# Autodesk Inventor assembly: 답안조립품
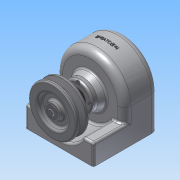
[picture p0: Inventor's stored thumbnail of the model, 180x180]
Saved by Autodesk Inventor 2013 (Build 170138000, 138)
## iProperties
Created: 2015-02
Part Number: 답안조립품
Document SubType Name: Assembly
Designer: Administrator
Author: Administrator
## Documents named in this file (14)
- C:\Documents and Settings\Administrator\바탕 화면\450214V1015\답안조립품.iam
- C:\Documents and Settings\Administrator\바탕 화면\450214V1015\1-본체.ipt
- C:\Documents and Settings\Administrator\바탕 화면\450214V1015\베어링 6001.ipt
- C:\Documents and Settings\Administrator\바탕 화면\450214V1015\축.ipt
- C:\Documents and Settings\Administrator\바탕 화면\450214V1015\키5x5.ipt
- C:\Documents and Settings\Administrator\바탕 화면\450214V1015\5-스퍼기어.ipt
- C:\Documents and Settings\Administrator\바탕 화면\450214V1015\축커버.ipt
- C:\Documents and Settings\Administrator\바탕 화면\450214V1015\M3x0.5.ipt
- C:\Documents and Settings\Administrator\바탕 화면\450214V1015\오일실.ipt
- C:\Documents and Settings\Administrator\바탕 화면\450214V1015\키4x4.ipt
- C:\Documents and Settings\Administrator\바탕 화면\450214V1015\4-V-벨트풀리.ipt
- C:\Documents and Settings\Administrator\바탕 화면\450214V1015\와샤.ipt
- C:\Documents and Settings\Administrator\바탕 화면\450214V1015\M5x0.8.ipt
- M5x0.8.ipt
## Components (7 placed, 4 different names)
1. 1-본체:1
2. 4-V-벨트풀리:1 — 각도:4
3. M5x0.8:1 — 각도:5
4. M3x0.5:1
5. M3x0.5:2
6. M3x0.5:3
7. M3x0.5:4
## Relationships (2: Angle 2)
- 각도:4 [Angle]: 4-V-벨트풀리:1
- 각도:5 [Angle]: M5x0.8:1
